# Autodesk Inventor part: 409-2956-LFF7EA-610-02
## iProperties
Created: 2011-01
Part Number: 409-2956-LFF7EA-610-02
Cost Center: 0 lbmass
Material: A36 STEEL PLATE
Document SubType Name: Sheet Metal
Designer: S. Boerckel
Authority: 0 in^3
Mass: 1949.37 g
Surface Area: 1086.35 cm^2
Volume: 248.011 cm^3
Density: 7.86 g/cm^3
Flat Pattern Width: 17.78 cm
Flat Pattern Length: 29.1252 cm
Flat Pattern Area: 517.846 cm^2
Sheet Metal Rule: 3/16"Thk
Description: VERTICAL SUPPORT PLATE
SaveDate: 2008-01-15
SaveTime: 10:24
FileName: Sheet Metal
Wide: =<Flat Pattern Width>cm
Length: =<Flat Pattern Length>cm
Thickness: 0.1875 in
SMR: =<Sheet Metal Rule> - <Material>
Author: S. Boerckel
Revision Number: 0
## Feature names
1. Plate1
2. Plate2
3. Bend1
